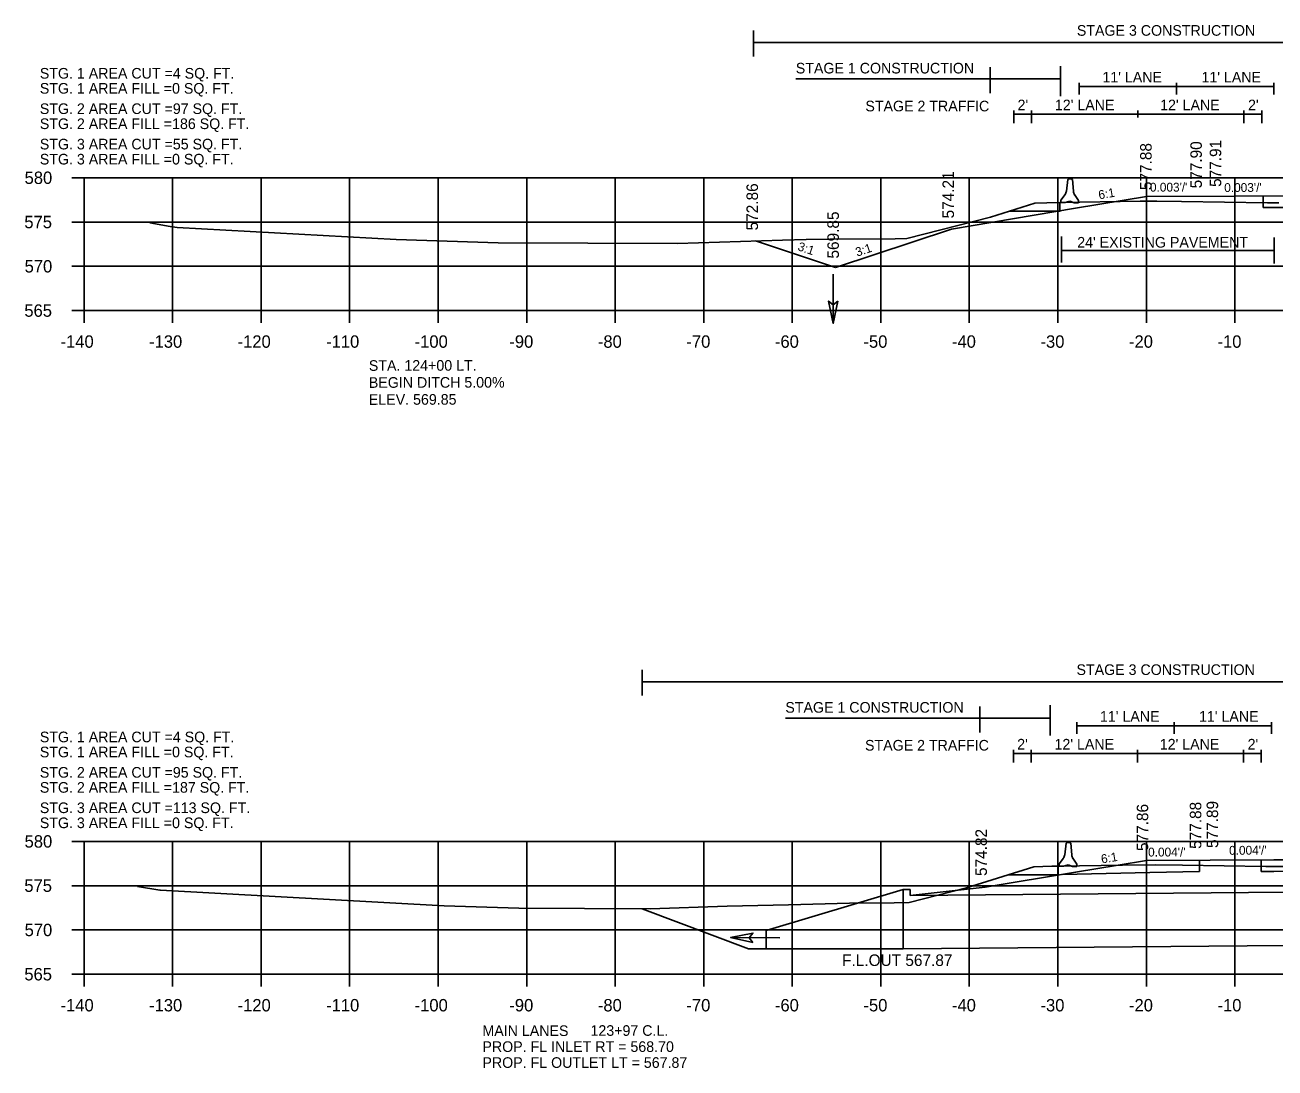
# Model space of a CAD drawing. Extents: x 642114 to 642416, y 286928 to 293347.
# Drawn here: x 642113.6 to 642254.8, y 291404.1 to 291522 of the extents above; entities that cross this region are included whole.
import ezdxf

# ---------------------------------------------------------------- set-up
doc = ezdxf.new("R2010")
doc.units = 0
for name, color, linetype in [('59', 7, 'Continuous'), ('Level 24', 7, 'Continuous'), ('Level 43', 7, 'Continuous'), ('Level 58', 7, 'Continuous'), ('R_Axis', 7, 'Continuous'), ('R_Axis Annot', 7, 'Continuous'), ('R_Draft', 7, 'Continuous'), ('R_Exist Surface', 7, 'Continuous'), ('R_Exist Surface Annot', 7, 'Continuous'), ('R_Fin Surface', 7, 'Continuous'), ('R_Grid', 7, 'Continuous'), ('R_MOT Barrier', 7, 'Continuous'), ('R_Water', 7, 'Continuous'), ('R_Xsect Elev', 7, 'Continuous'), ('R_Xsect Slope', 7, 'Continuous')]:
    doc.layers.add(name, color=color, linetype=linetype)

# ---------------------------------------------------------------- blocks, each defined once
blk = doc.blocks.new('BARRIER WALL X-SECTION')
at = {"layer": 'R_MOT Barrier'}
for p, q in [((0.8, 2.59), (0.63, 1.29)), ((0.8, 2.59), (0.87, 2.65)), ((0.87, 2.65), (1.24, 2.64)), ((1.24, 2.64), (1.31, 2.58)), ((1.31, 2.58), (1.42, 1.27)), ((0.48, 0.9), (0, 0.25)), ((0, 0.25), (0, 0)), ((0.5, -0.01), (0, 0)), ((0.5, -0.01), (1, 0.15)), ((1, 0.15), (1.5, -0.03)), ((1.56, 0.88), (2, 0.21)), ((2, 0.21), (2, -0.04)), ((1.5, -0.03), (2, -0.04))]:
    blk.add_line(p, q, dxfattribs=at)
for centre, start, end in [((-0.2, 1.39), 323.8622, 352.8452), ((2.25, 1.34), 184.8632, 213.8462)]:
    blk.add_arc(centre, 0.833, start, end, dxfattribs=at)
blk = doc.blocks.new('FA')
at = {"layer": 'Level 43'}
blk.add_lwpolyline([(7.94, 0), (0, 0)], dxfattribs=at)
at = {"layer": 'Level 58'}
blk.add_lwpolyline([(4.34, 0.75), (7.94, 0), (4.34, -0.75), (4.94, 0)], close=True, dxfattribs=at)

msp = doc.modelspace()

# ---------------------------------------------------------------- linework, layer by layer
at = {"layer": 'R_Axis'}
for p, q in [((642118.84, 291504.7), (642120.24, 291504.7)), ((642120.24, 291489.7), (642120.24, 291504.7)), ((642118.84, 291499.7), (642120.24, 291499.7)), ((642118.84, 291494.7), (642120.24, 291494.7)), ((642118.84, 291489.7), (642120.24, 291489.7)), ((642120.24, 291489.7), (642400.24, 291489.7)), ((642120.24, 291488.3), (642120.24, 291489.7)), ((642130.24, 291488.3), (642130.24, 291489.7)), ((642140.24, 291488.3), (642140.24, 291489.7)), ((642150.24, 291488.3), (642150.24, 291489.7)), ((642160.24, 291488.3), (642160.24, 291489.7)), ((642170.24, 291488.3), (642170.24, 291489.7)), ((642180.24, 291488.3), (642180.24, 291489.7)), ((642190.24, 291488.3), (642190.24, 291489.7)), ((642200.24, 291488.3), (642200.24, 291489.7)), ((642210.24, 291488.3), (642210.24, 291489.7)), ((642220.24, 291488.3), (642220.24, 291489.7)), ((642230.24, 291488.3), (642230.24, 291489.7)), ((642240.24, 291488.3), (642240.24, 291489.7)), ((642250.24, 291488.3), (642250.24, 291489.7)), ((642118.84, 291429.74), (642120.24, 291429.74)), ((642120.24, 291414.74), (642120.24, 291429.74)), ((642118.84, 291424.74), (642120.24, 291424.74)), ((642118.84, 291419.74), (642120.24, 291419.74)), ((642118.84, 291414.74), (642120.24, 291414.74)), ((642120.24, 291414.74), (642400.24, 291414.74)), ((642120.24, 291413.34), (642120.24, 291414.74)), ((642130.24, 291413.34), (642130.24, 291414.74)), ((642140.24, 291413.34), (642140.24, 291414.74)), ((642150.24, 291413.34), (642150.24, 291414.74)), ((642160.24, 291413.34), (642160.24, 291414.74)), ((642170.24, 291413.34), (642170.24, 291414.74)), ((642180.24, 291413.34), (642180.24, 291414.74)), ((642190.24, 291413.34), (642190.24, 291414.74)), ((642200.24, 291413.34), (642200.24, 291414.74)), ((642210.24, 291413.34), (642210.24, 291414.74)), ((642220.24, 291413.34), (642220.24, 291414.74)), ((642230.24, 291413.34), (642230.24, 291414.74)), ((642240.24, 291413.34), (642240.24, 291414.74)), ((642250.24, 291413.34), (642250.24, 291414.74))]:
    msp.add_line(p, q, dxfattribs=at)
at = {"layer": 'R_Exist Surface'}
for points in [[(642253.43, 291502.62), (642253.43, 291501.33)], [(642253.43, 291501.33), (642260.24, 291501.35), (642274.24, 291501.07), (642288.23, 291500.79)], [(642246.24, 291427.62), (642246.24, 291426.33)], [(642253.23, 291427.65), (642253.23, 291426.36)], [(642230.78, 291426.02), (642240.65, 291426.22), (642246.24, 291426.33)], [(642253.23, 291426.36), (642254.64, 291426.36), (642260.24, 291426.38)]]:
    msp.add_lwpolyline(points, dxfattribs=at)
at = {"layer": 'R_Exist Surface Annot'}
for points in [[(642127.65, 291499.6), (642129.96, 291499.2), (642130.76, 291499.07), (642155.51, 291497.71), (642167.03, 291497.36), (642187.28, 291497.26), (642199.15, 291497.64), (642201.81, 291497.71), (642204.47, 291497.77), (642211.85, 291497.82), (642213.19, 291497.85), (642222.63, 291500.26), (642227.64, 291501.82), (642228.99, 291501.87), (642230.48, 291501.91), (642239.53, 291502.04), (642241.43, 291502.06), (642244.23, 291502.02), (642253.93, 291501.87), (642255.19, 291501.88)], [(642126.26, 291424.65), (642128.79, 291424.23), (642128.81, 291424.22), (642128.86, 291424.22), (642160.93, 291422.46), (642169.36, 291422.2), (642184.19, 291422.13), (642192.9, 291422.41), (642199.8, 291422.59), (642206.7, 291422.77), (642211.77, 291422.8), (642213.44, 291422.84), (642219.91, 291424.49), (642227.52, 291426.86), (642229.56, 291426.93), (642230.29, 291426.95), (642237.54, 291427.05), (642241.23, 291427.1), (642244.34, 291427.05), (642253.72, 291426.91), (642255.69, 291426.91)]]:
    msp.add_lwpolyline(points, dxfattribs=at)
at = {"layer": 'R_Fin Surface'}
for points in [[(642205.14, 291494.55), (642218.24, 291498.91), (642232.25, 291501.25), (642240.24, 291502.58)], [(642240.24, 291502.58), (642260.24, 291502.65), (642274.24, 291502.37), (642280.24, 291502.13), (642288.23, 291500.79), (642302.24, 291498.46), (642317.42, 291493.4)], [(642196.1, 291497.56), (642205.14, 291494.55)], [(642222.02, 291424.56), (642232.25, 291426.26), (642237.04, 291427.06), (642240.24, 291427.6)], [(642240.24, 291427.6), (642254.64, 291427.65), (642260.24, 291427.67)], [(642213.55, 291423.62), (642222.02, 291424.56)], [(642197.28, 291417.61), (642195.28, 291417.61), (642183.28, 291422.14)]]:
    msp.add_lwpolyline(points, dxfattribs=at)
at = {"layer": 'R_Grid'}
for p, q in [((642120.24, 291504.7), (642400.24, 291504.7)), ((642120.24, 291489.7), (642120.24, 291504.7)), ((642130.24, 291489.7), (642130.24, 291504.7)), ((642140.24, 291489.7), (642140.24, 291504.7)), ((642150.24, 291489.7), (642150.24, 291504.7)), ((642160.24, 291489.7), (642160.24, 291504.7)), ((642170.24, 291489.7), (642170.24, 291504.7)), ((642180.24, 291489.7), (642180.24, 291504.7)), ((642190.24, 291489.7), (642190.24, 291504.7)), ((642200.24, 291489.7), (642200.24, 291504.7)), ((642210.24, 291489.7), (642210.24, 291504.7)), ((642220.24, 291489.7), (642220.24, 291504.7)), ((642230.24, 291489.7), (642230.24, 291504.7)), ((642240.24, 291489.7), (642240.24, 291504.7)), ((642250.24, 291489.7), (642250.24, 291504.7)), ((642120.24, 291499.7), (642400.24, 291499.7)), ((642120.24, 291494.7), (642400.24, 291494.7)), ((642120.24, 291489.7), (642400.24, 291489.7)), ((642120.24, 291429.74), (642400.24, 291429.74)), ((642120.24, 291414.74), (642120.24, 291429.74)), ((642130.24, 291414.74), (642130.24, 291429.74)), ((642140.24, 291414.74), (642140.24, 291429.74)), ((642150.24, 291414.74), (642150.24, 291429.74)), ((642160.24, 291414.74), (642160.24, 291429.74)), ((642170.24, 291414.74), (642170.24, 291429.74)), ((642180.24, 291414.74), (642180.24, 291429.74)), ((642190.24, 291414.74), (642190.24, 291429.74)), ((642200.24, 291414.74), (642200.24, 291429.74)), ((642210.24, 291414.74), (642210.24, 291429.74)), ((642220.24, 291414.74), (642220.24, 291429.74)), ((642230.24, 291414.74), (642230.24, 291429.74)), ((642240.24, 291414.74), (642240.24, 291429.74)), ((642250.24, 291414.74), (642250.24, 291429.74)), ((642120.24, 291424.74), (642400.24, 291424.74)), ((642120.24, 291419.74), (642400.24, 291419.74)), ((642120.24, 291414.74), (642400.24, 291414.74))]:
    msp.add_line(p, q, dxfattribs=at)
at = {"layer": 'R_Water'}
for points in [[(642212.78, 291424.31), (642197.28, 291419.67)], [(642213.55, 291424.31), (642212.78, 291424.31)], [(642212.78, 291423.87), (642212.78, 291424.31)], [(642212.78, 291417.61), (642212.78, 291423.87)], [(642213.55, 291423.62), (642307.01, 291424.44)], [(642213.55, 291423.62), (642213.55, 291424.31)], [(642197.28, 291417.61), (642197.28, 291419.67)], [(642212.78, 291417.61), (642307.77, 291418.44)], [(642212.78, 291417.61), (642197.28, 291417.61)]]:
    msp.add_lwpolyline(points, dxfattribs=at)
at = {"layer": 'R_Xsect Elev'}
for p, q in [((642195.87, 291518.41), (642195.87, 291521.33)), ((642195.87, 291519.98), (642282.8, 291519.98)), ((642222.6, 291514.25), (642222.6, 291517.18)), ((642230.56, 291514.39), (642230.56, 291517.32)), ((642200.64, 291515.86), (642230.56, 291515.86)), ((642232.66, 291514.1), (642232.66, 291515.42)), ((642243.66, 291514.1), (642243.66, 291515.42)), ((642254.66, 291514.1), (642254.66, 291515.42)), ((642230.56, 291513.9), (642230.56, 291515)), ((642232.66, 291515), (642254.66, 291515)), ((642225.27, 291510.85), (642225.27, 291512.28)), ((642227.27, 291510.85), (642227.27, 291512.28)), ((642239.27, 291511.5), (642239.27, 291512.28)), ((642251.27, 291510.85), (642251.27, 291512.28)), ((642253.27, 291510.85), (642253.27, 291512.28)), ((642225.27, 291511.87), (642253.27, 291511.87)), ((642230.67, 291495.12), (642230.67, 291498.05)), ((642254.67, 291495.03), (642254.67, 291497.96)), ((642230.67, 291496.47), (642254.67, 291496.47)), ((642183.28, 291446.21), (642183.28, 291449.13)), ((642183.28, 291447.78), (642282.75, 291447.78)), ((642221.43, 291442.05), (642221.43, 291444.98)), ((642229.39, 291442.19), (642229.39, 291445.12)), ((642199.46, 291443.66), (642229.39, 291443.66)), ((642232.37, 291441.9), (642232.37, 291443.22)), ((642243.37, 291441.9), (642243.37, 291443.22)), ((642254.37, 291441.9), (642254.37, 291443.22)), ((642229.39, 291441.7), (642229.39, 291442.8)), ((642232.37, 291442.8), (642254.37, 291442.8)), ((642225.23, 291438.65), (642225.23, 291440.08)), ((642225.23, 291439.67), (642253.23, 291439.67)), ((642227.23, 291438.65), (642227.23, 291440.08)), ((642239.23, 291438.65), (642239.23, 291440.08)), ((642251.23, 291438.65), (642251.23, 291440.08)), ((642253.23, 291438.65), (642253.23, 291440.08))]:
    msp.add_line(p, q, dxfattribs=at)
for points in [[(642224.74, 291500.91), (642230.48, 291500.91), (642230.48, 291501.91)], [(642224.61, 291425.95), (642230.29, 291425.95), (642230.29, 291426.95)]]:
    msp.add_lwpolyline(points, dxfattribs=at)

# ---------------------------------------------------------------- block references
for p in [(642230.58, 291501.91), (642230.39, 291426.95)]:
    msp.add_blockref('BARRIER WALL X-SECTION', p, dxfattribs=at)
at = {"layer": 'R_Xsect Elev', "xscale": 0.7}
for p, yscale, rotation in [((642204.87, 291493.81), 0.7, -90.00000000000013), ((642198.83, 291418.86), 0.6999999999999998, 179.90549921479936)]:
    msp.add_blockref('FA', p, dxfattribs=dict(at, yscale=yscale, rotation=rotation))

# ---------------------------------------------------------------- texts
at = {"layer": '59'}
for s, p in [(' 577.88', (642240.84, 291502.82)), (' 577.90', (642246.51, 291503.02)), (' 577.91', (642248.7, 291503.18)), (' 574.21', (642218.51, 291499.62)), (' 572.86', (642196.37, 291498.27)), (' 569.85', (642205.51, 291495.09)), (' 577.86', (642240.45, 291428.17)), (' 577.88', (642246.45, 291428.41)), (' 577.89', (642248.35, 291428.51)), (' 574.82', (642222.23, 291425.35))]:
    msp.add_text(s, height=1.3, rotation=90, dxfattribs=at).set_placement(p)
msp.add_text('F.L.OUT 567.87', height=1.3, dxfattribs=at).set_placement((642205.87, 291415.67))
at = {"layer": 'Level 24'}
for s, p in [('MAIN LANES', (642165.24, 291407.76)), ('123+97 C.L.', (642177.45, 291407.78)), ('PROP. FL INLET RT = 568.70', (642165.24, 291405.96)), ('PROP. FL OUTLET LT = 567.87', (642165.24, 291404.16))]:
    msp.add_text(s, height=1.2, rotation=0.0044, dxfattribs=at).set_placement(p)
at = {"layer": 'R_Axis Annot'}
for s, p in [('580', (642113.52, 291504)), ('575', (642113.49, 291499)), ('570', (642113.52, 291494)), ('565', (642113.49, 291489)), ('-140', (642117.58, 291485.5)), ('-130', (642127.58, 291485.5)), ('-120', (642137.58, 291485.5)), ('-110', (642147.58, 291485.5)), ('-100', (642157.58, 291485.5)), ('-90', (642168.28, 291485.5)), ('-80', (642178.28, 291485.5)), ('-70', (642188.28, 291485.5)), ('-60', (642198.28, 291485.5)), ('-50', (642208.28, 291485.5)), ('-40', (642218.28, 291485.5)), ('-30', (642228.28, 291485.5)), ('-20', (642238.28, 291485.5)), ('-10', (642248.28, 291485.5)), ('580', (642113.52, 291429.04)), ('575', (642113.49, 291424.04)), ('570', (642113.52, 291419.04)), ('565', (642113.49, 291414.04)), ('-140', (642117.58, 291410.54)), ('-130', (642127.58, 291410.54)), ('-120', (642137.58, 291410.54)), ('-110', (642147.58, 291410.54)), ('-100', (642157.58, 291410.54)), ('-90', (642168.28, 291410.54)), ('-80', (642178.28, 291410.54)), ('-70', (642188.28, 291410.54)), ('-60', (642198.28, 291410.54)), ('-50', (642208.28, 291410.54)), ('-40', (642218.28, 291410.54)), ('-30', (642228.28, 291410.54)), ('-20', (642238.28, 291410.54)), ('-10', (642248.28, 291410.54))]:
    msp.add_text(s, height=1.4, dxfattribs=at).set_placement(p)
at = {"layer": 'R_Draft'}
for s, p in [('STG. 1 AREA CUT =4 SQ. FT.', (642115.24, 291515.9)), ('STG. 1 AREA FILL =0 SQ. FT.', (642115.24, 291514.2)), ('STG. 2 AREA CUT =97 SQ. FT.', (642115.24, 291511.9)), ('STG. 2 AREA FILL =186 SQ. FT.', (642115.24, 291510.2)), ('STG. 3 AREA CUT =55 SQ. FT.', (642115.24, 291507.9)), ('STG. 3 AREA FILL =0 SQ. FT.', (642115.24, 291506.2)), ('STG. 1 AREA CUT =4 SQ. FT.', (642115.24, 291440.94)), ('STG. 1 AREA FILL =0 SQ. FT.', (642115.24, 291439.24)), ('STG. 2 AREA CUT =95 SQ. FT.', (642115.24, 291436.94)), ('STG. 2 AREA FILL =187 SQ. FT.', (642115.24, 291435.24)), ('STG. 3 AREA CUT =113 SQ. FT.', (642115.24, 291432.94)), ('STG. 3 AREA FILL =0 SQ. FT.', (642115.24, 291431.24))]:
    msp.add_text(s, height=1.2, dxfattribs=at).set_placement(p)
at = {"layer": 'R_Xsect Elev'}
for s, p in [('STAGE 3 CONSTRUCTION', (642232.39, 291520.74)), ('STAGE 1 CONSTRUCTION', (642200.64, 291516.48)), ("11' LANE", (642235.28, 291515.46)), ("11' LANE", (642246.47, 291515.46)), ('STAGE 2 TRAFFIC', (642208.5, 291512.2)), ("2'", (642225.69, 291512.32)), ("12' LANE", (642229.91, 291512.32)), ("12' LANE", (642241.8, 291512.32)), ("2'", (642251.73, 291512.32)), ("24' EXISTING PAVEMENT", (642232.43, 291496.81)), ('STAGE 3 CONSTRUCTION', (642232.35, 291448.54)), ('STAGE 1 CONSTRUCTION', (642199.46, 291444.28)), ("11' LANE", (642235, 291443.26)), ("11' LANE", (642246.19, 291443.26)), ('STAGE 2 TRAFFIC', (642208.46, 291440)), ("2'", (642225.65, 291440.12)), ("12' LANE", (642229.87, 291440.12)), ("12' LANE", (642241.76, 291440.12)), ("2'", (642251.68, 291440.12))]:
    msp.add_text(s, height=1.2, dxfattribs=at).set_placement(p)
for s, p in [('STA. 124+00 LT.', (642152.41, 291482.89)), ('BEGIN DITCH 5.00%', (642152.41, 291480.97)), ('ELEV. 569.85', (642152.41, 291479.05))]:
    msp.add_text(s, height=1.2, rotation=0.107, dxfattribs=at).set_placement(p)
at = {"layer": 'R_Xsect Slope'}
for s, rotation, p in [("0.003'/'", 0.1879, (642240.65, 291503.13)), ("0.003'/'", 0.1879, (642249.04, 291503.09)), ('6:1', 9.4642, (642234.91, 291502.26)), ('3:1', 341.5668, (642200.78, 291496.53)), ('3:1', 18.4332, (642207.57, 291495.78)), ("0.004'/'", 0.2108, (642240.44, 291428.03)), ("0.004'/'", 0.2108, (642249.59, 291428.23)), ('6:1', 9.4642, (642235.21, 291427.24))]:
    msp.add_text(s, height=1, rotation=rotation, dxfattribs=at).set_placement(p)

doc.saveas('drawing.dxf')
